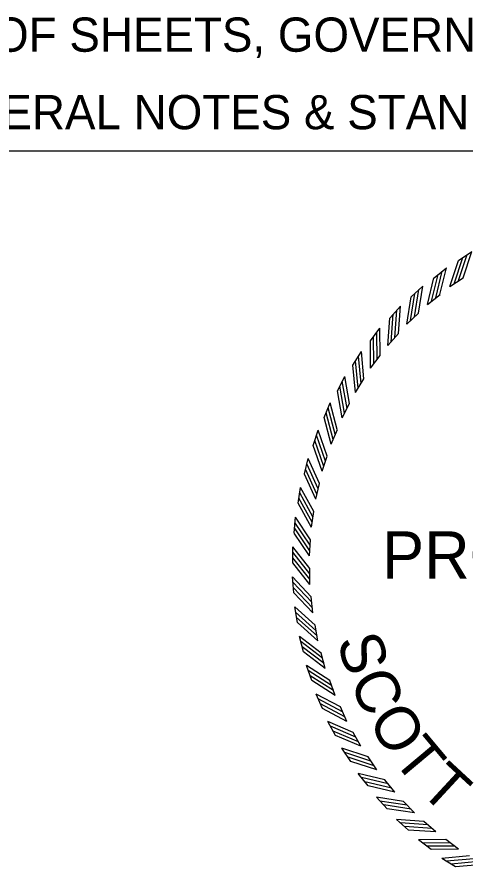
# Model space of a CAD drawing. Extents: x -1197 to 1681, y -1031 to 1021.
# Drawn here: x 1325.7 to 1479.2, y 644.8 to 936 of the extents above; entities that cross this region are included whole.
import ezdxf

# ---------------------------------------------------------------- set-up
doc = ezdxf.new("R2010")
doc.units = 0
doc.layers.add('R_Border Prem', color=7, linetype='Continuous')
doc.layers.add('R_Grid', color=7, linetype='Continuous')

msp = doc.modelspace()

# ---------------------------------------------------------------- linework, layer by layer
at = {"layer": 'R_Border Prem'}
msp.add_line((1249.94, 890.16), (1680.94, 890.16), dxfattribs=at)
at = {"layer": 'R_Grid'}
for p, q in [((1476.92, 852.61), (1481.45, 855.63)), ((1468.55, 846.7), (1472.81, 850.08)), ((1473.96, 843.68), (1478.5, 846.7)), ((1460.69, 840.11), (1464.66, 843.83)), ((1466.33, 837.55), (1470.6, 840.93)), ((1453.4, 832.89), (1457.05, 836.93)), ((1459.23, 830.81), (1463.21, 834.54)), ((1446.73, 825.1), (1450.03, 829.42)), ((1452.72, 823.5), (1456.37, 827.55)), ((1440.73, 816.78), (1443.66, 821.37)), ((1446.83, 815.69), (1450.14, 820.02)), ((1435.43, 808), (1437.98, 812.81)), ((1441.6, 807.41), (1444.54, 812)), ((1430.88, 798.81), (1433.02, 803.81)), ((1437.08, 798.73), (1439.63, 803.55)), ((1427.11, 789.27), (1428.83, 794.44)), ((1433.29, 789.71), (1435.43, 794.72)), ((1424.13, 779.46), (1425.42, 784.75)), ((1430.25, 780.4), (1431.98, 785.57)), ((1421.97, 769.43), (1422.82, 774.81)), ((1428, 770.88), (1429.29, 776.17)), ((1426.54, 761.2), (1427.39, 766.59)), ((1420.65, 759.26), (1421.05, 764.69)), ((1420.18, 749.02), (1420.13, 754.46)), ((1425.88, 751.43), (1426.28, 756.87)), ((1426.03, 741.65), (1425.98, 747.1)), ((1420.55, 738.77), (1420.05, 744.19)), ((1426.99, 731.91), (1426.49, 737.34)), ((1421.77, 728.58), (1420.82, 733.94)), ((1428.76, 722.28), (1427.81, 727.65)), ((1423.82, 718.54), (1422.43, 723.8)), ((1431.31, 712.83), (1429.92, 718.1)), ((1426.69, 708.69), (1424.88, 713.82)), ((1434.63, 703.62), (1432.81, 708.76)), ((1430.37, 699.12), (1428.14, 704.08)), ((1438.7, 694.72), (1436.46, 699.7)), ((1434.83, 689.88), (1432.2, 694.64)), ((1443.49, 686.19), (1440.85, 690.96)), ((1440.04, 681.04), (1437.02, 685.57)), ((1448.97, 678.08), (1445.95, 682.62)), ((1445.95, 672.67), (1442.57, 676.93)), ((1455.1, 670.45), (1451.71, 674.72)), ((1452.54, 664.81), (1448.82, 668.78)), ((1461.84, 663.35), (1458.11, 667.33)), ((1459.76, 657.52), (1455.72, 661.17)), ((1469.15, 656.84), (1465.1, 660.49)), ((1467.55, 650.85), (1463.22, 654.15)), ((1476.96, 650.95), (1472.63, 654.26)), ((1475.86, 644.85), (1471.28, 647.78))]:
    msp.add_line(p, q, dxfattribs=at)
for points in [[(1475.42, 844.63), (1478.39, 853.56)], [(1476.97, 845.71), (1479.94, 854.64)], [(1478.49, 846.7), (1481.45, 855.64)], [(1473.96, 843.67), (1476.92, 852.6)], [(1467.71, 838.61), (1469.93, 847.76)], [(1469.16, 839.82), (1471.38, 848.97)], [(1470.59, 840.93), (1472.81, 850.08)], [(1466.33, 837.54), (1468.54, 846.69)], [(1461.87, 833.31), (1463.32, 842.61)], [(1463.2, 834.53), (1464.66, 843.83)], [(1459.23, 830.8), (1460.69, 840.1)], [(1460.52, 831.98), (1461.97, 841.28)], [(1455.14, 826.21), (1455.82, 835.6)], [(1456.37, 827.55), (1457.05, 836.93)], [(1452.72, 823.49), (1453.4, 832.88)], [(1453.9, 824.78), (1454.58, 834.17)], [(1449.02, 818.59), (1448.92, 828)], [(1450.13, 820.02), (1450.03, 829.43)], [(1446.83, 815.68), (1446.73, 825.09)], [(1447.9, 817.06), (1447.81, 826.47)], [(1444.53, 812), (1443.66, 821.37)], [(1442.56, 808.87), (1441.69, 818.24)], [(1443.54, 810.48), (1442.67, 819.85)], [(1441.6, 807.4), (1440.73, 816.77)], [(1439.62, 803.55), (1437.98, 812.81)], [(1437.91, 800.26), (1436.27, 809.53)], [(1438.76, 801.95), (1437.12, 811.22)], [(1437.08, 798.72), (1435.43, 807.99)], [(1435.42, 794.72), (1433.02, 803.82)], [(1434.7, 793.06), (1432.29, 802.16)], [(1433.29, 789.7), (1430.88, 798.8)], [(1433.99, 791.3), (1431.59, 800.4)], [(1431.38, 783.86), (1428.23, 792.73)], [(1431.97, 785.57), (1428.82, 794.44)], [(1430.26, 780.39), (1427.11, 789.27)], [(1430.82, 782.05), (1427.68, 790.92)], [(1429.28, 776.17), (1425.41, 784.75)], [(1428.43, 772.57), (1424.56, 781.15)], [(1428.84, 774.41), (1424.97, 782.99)], [(1428, 770.87), (1424.13, 779.45)], [(1427.38, 766.58), (1422.82, 774.81)], [(1427.08, 764.79), (1422.52, 773.03)], [(1426.54, 761.19), (1421.98, 769.42)], [(1426.83, 762.92), (1422.27, 771.15)], [(1426.13, 755.06), (1420.9, 762.89)], [(1426.28, 756.87), (1421.05, 764.69)], [(1426.03, 753.17), (1420.8, 761)], [(1425.89, 751.43), (1420.66, 759.25)], [(1425.98, 747.09), (1420.12, 754.46)], [(1425.98, 745.28), (1420.12, 752.65)], [(1426.04, 743.39), (1420.18, 750.76)], [(1426.04, 741.64), (1420.18, 749.01)], [(1426.49, 737.33), (1420.04, 744.19)], [(1426.64, 735.52), (1420.19, 742.38)], [(1426.86, 733.65), (1420.41, 740.51)], [(1427, 731.9), (1420.55, 738.76)], [(1427.81, 727.64), (1420.82, 733.95)], [(1428.1, 725.85), (1421.11, 732.16)], [(1428.47, 724), (1421.48, 730.31)], [(1428.76, 722.27), (1421.77, 728.58)], [(1429.92, 718.1), (1422.43, 723.8)], [(1430.36, 716.34), (1422.87, 722.04)], [(1430.88, 714.52), (1423.4, 720.23)], [(1431.31, 712.82), (1423.83, 718.53)], [(1432.81, 708.76), (1424.88, 713.82)], [(1433.4, 707.04), (1425.46, 712.11)], [(1434.07, 705.27), (1426.13, 710.34)], [(1434.64, 703.62), (1426.7, 708.69)], [(1436.46, 699.69), (1428.14, 704.08)], [(1437.19, 698.03), (1428.87, 702.42)], [(1438, 696.32), (1429.68, 700.72)], [(1438.71, 694.72), (1430.38, 699.11)], [(1440.85, 690.95), (1432.19, 694.65)], [(1441.71, 689.36), (1433.05, 693.05)], [(1442.67, 687.72), (1434.01, 691.42)], [(1443.5, 686.18), (1434.84, 689.88)], [(1445.95, 682.61), (1437.01, 685.57)], [(1446.94, 681.09), (1438, 684.06)], [(1448.02, 679.54), (1439.09, 682.51)], [(1448.98, 678.08), (1440.04, 681.04)], [(1451.71, 674.71), (1442.57, 676.93)], [(1452.83, 673.28), (1443.68, 675.5)], [(1454.04, 671.83), (1444.89, 674.05)], [(1455.11, 670.45), (1445.96, 672.66)], [(1458.11, 667.32), (1448.81, 668.78)], [(1459.34, 665.99), (1450.04, 667.44)], [(1460.67, 664.64), (1451.36, 666.09)], [(1461.85, 663.35), (1452.55, 664.81)], [(1465.1, 660.49), (1455.71, 661.17)], [(1466.44, 659.26), (1457.05, 659.94)], [(1467.87, 658.02), (1458.48, 658.7)], [(1469.15, 656.84), (1459.77, 657.52)], [(1472.63, 654.25), (1463.22, 654.15)], [(1474.06, 653.14), (1464.65, 653.04)], [(1475.59, 652.02), (1466.18, 651.93)], [(1476.97, 650.95), (1467.56, 650.85)], [(1480.65, 648.65), (1471.28, 647.78)], [(1482.17, 647.66), (1472.79, 646.79)], [(1483.78, 646.68), (1474.41, 645.81)], [(1485.25, 645.72), (1475.87, 644.85)]]:
    msp.add_lwpolyline(points, dxfattribs=at)

# ---------------------------------------------------------------- texts
at = {"layer": 'R_Border Prem'}
for s, p in [('INDEX OF SHEETS, GOVERNING SPECIFICATIONS ', (1265.21, 924.09)), ('GENERAL NOTES & STANDARD DRAWINGS', (1286.35, 897.54))]:
    msp.add_text(s, height=11.724, dxfattribs=at).set_placement(p)
at = {"layer": 'R_Grid'}
msp.add_text('PROFESSIONAL', height=16.1547, dxfattribs=at).set_placement((1450.76, 743.66))
for s, rotation, p in [('S', 286.9475, (1435.15, 722.44)), ('C', 294.2435, (1439.34, 708.73)), ('O', 301.9044, (1445.56, 695.02)), ('T', 309.93, (1453.98, 681.69)), ('T', 317.226, (1463.18, 670.7))]:
    msp.add_text(s, height=15.03, rotation=rotation, dxfattribs=at).set_placement(p)

doc.saveas('drawing.dxf')
